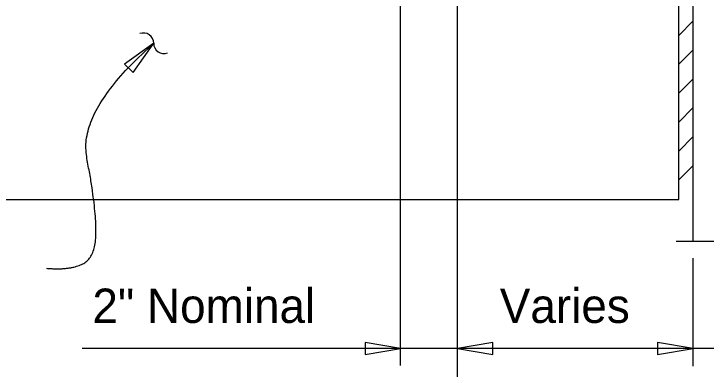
# Model space of a CAD drawing. Extents: x 21629.5 to 21698.8, y 56199.4 to 56237.6.
# Drawn here: x 21656.357 to 21660.425, y 56224.061 to 56226.147 of the extents above; entities that cross this region are included whole.
import ezdxf

# ---------------------------------------------------------------- set-up
doc = ezdxf.new("R2010")
doc.units = 0
for name, color, linetype in [('Dimension', 7, 'Continuous'), ('ExistSuperStruct', 7, 'Continuous'), ('Miscellaneous', 7, 'Continuous'), ('TextStructures', 7, 'Continuous')]:
    doc.layers.add(name, color=color, linetype=linetype)

msp = doc.modelspace()

# ---------------------------------------------------------------- linework, layer by layer
at = {"layer": 'Dimension'}
for p, q in [((21658.6296, 56224.0819), (21658.6296, 56227.9716)), ((21658.963, 56223.3626), (21658.963, 56227.7178)), ((21660.3479, 56224.0786), (21660.3479, 56224.7118)), ((21660.9324, 56224.1819), (21656.7577, 56224.1819))]:
    msp.add_line(p, q, dxfattribs=at)
for points in [[(21657.1791, 56225.9743), (21657.0072, 56225.8517), (21657.0571, 56225.8019)], [(21658.6298, 56224.182), (21658.4215, 56224.2172), (21658.4215, 56224.1467)], [(21658.9629, 56224.1819), (21659.1712, 56224.1466), (21659.1712, 56224.2172)], [(21660.3479, 56224.1819), (21660.1396, 56224.2172), (21660.1396, 56224.1466)]]:
    msp.add_lwpolyline(points, close=True, dxfattribs=at)
msp.add_lwpolyline([(21660.2479, 56224.8118), (21661.5906, 56224.8118), (21661.5906, 56224.8893), (21661.6244, 56224.8118), (21661.6581, 56224.7343), (21661.6581, 56224.8118), (21662.9479, 56224.8118)], dxfattribs=at)
for centre, start, end in [((21657.1189, 56225.9755), 359.2799, 111.0071), ((21657.2382, 56225.974), 179.2799, 291.0071)]:
    msp.add_arc(centre, 0.0596, start, end, dxfattribs=at)
for points in [[(21656.5495, 56224.6529), (21656.6855, 56224.6409), (21656.8395, 56224.717), (21656.8395, 56225.0232), (21656.7321, 56225.5802), (21657.1791, 56225.9743)], [(21659.813, 56222.9392), (21660.7364, 56222.9326), (21660.6521, 56223.8924), (21660.6527, 56224.1998), (21660.6527, 56224.2576), (21660.6205, 56224.2158), (21660.6061, 56224.1933), (21660.5982, 56224.1329), (21660.7387, 56224.07)]]:
    msp.add_open_spline(points, degree=2, dxfattribs=at)
at = {"layer": 'ExistSuperStruct'}
for p, q in [((21660.2645, 56225.0569), (21660.2645, 56227.8585)), ((21660.3479, 56224.8118), (21660.3479, 56227.8597)), ((21654.863, 56225.0569), (21660.2645, 56225.0569))]:
    msp.add_line(p, q, dxfattribs=at)
at = {"layer": 'Miscellaneous'}
for p, q in [((21660.2645, 56226.0206), (21660.3494, 56226.1055)), ((21660.2645, 56225.8509), (21660.3494, 56225.9358)), ((21660.2645, 56225.6812), (21660.3494, 56225.7661)), ((21660.2645, 56225.5115), (21660.3494, 56225.5964)), ((21660.2645, 56225.3418), (21660.3494, 56225.4267)), ((21660.2645, 56225.1721), (21660.3494, 56225.257))]:
    msp.add_line(p, q, dxfattribs=at)

# ---------------------------------------------------------------- texts
at = {"layer": 'TextStructures'}
for s, p in [('2" Nominal', (21656.8185, 56224.3321)), ('Varies', (21659.2122, 56224.3321))]:
    msp.add_text(s, height=0.2016, dxfattribs=at).set_placement(p)

doc.saveas('drawing.dxf')
